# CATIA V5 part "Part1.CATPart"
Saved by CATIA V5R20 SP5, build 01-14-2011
Part number: Part1
Material "Gold Metal": density 7860 kg/m3, Young's modulus 2e+11 Pa, Poisson ratio 0.266
Material "DS Gold": density 7860 kg/m3, Young's modulus 2e+11 Pa, Poisson ratio 0.266
Bounding box of the stored display mesh (mm): x -25 to 25, y -25 to 24.975, z -18 to 18
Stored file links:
  D:\zhonggao\Part1.CATPart
  C:\Program Files\Dassault Systemes\B20\intel_a\startup\materials\Catalog.CATMaterial
  C:\Program Files\Dassault Systemes\B20\intel_a\startup\materials\yellow_env_512x512.jpg
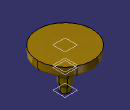
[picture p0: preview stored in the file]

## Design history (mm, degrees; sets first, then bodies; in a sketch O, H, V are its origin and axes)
Body1 (main body)
Body2, material "Gold Metal"
  Plane1: type Offset, RefPlane xy-plane, Offset 2
  Plane2: type Offset, RefPlane Plane1, Offset 2
  Plane3: type Offset, RefPlane Plane2, Offset 2
  Plane4: type Offset, RefPlane Plane3, Offset 2
  Plane5: type Offset, RefPlane Plane4, Offset 2
  Plane6: type Offset, RefPlane Plane5, Offset 2
  Sketch1 on Plane6, origin (0, 0, 12), H (1, 0, 0), V (0, 1, 0)
    circle A1 centre (0, 0) radius 25
    radius A1 = 25
  Sketch2 on Plane5, origin (0, 0, 10), H (1, 0, 0), V (0, 1, 0)
    circle A1 centre (0, 0) radius 24
    radius A1 = 24
  Sketch3 on Plane4, origin (0, 0, 8), H (1, 0, 0), V (0, 1, 0)
    circle A1 centre (0, 0) radius 20
    radius A1 = 20
  Sketch4 on Plane2, origin (0, 0, 4), H (1, 0, 0), V (0, 1, 0)
    circle A1 centre (0, 0) radius 10
    radius A1 = 10
  Sketch5 on Plane1, origin (0, 0, 2), H (1, 0, 0), V (0, 1, 0)
    circle A1 centre (0, 0) radius 5
    radius A1 = 5
  Plane7: type Offset, RefPlane Plane6, Offset 6
  Sketch6 on Plane7, origin (0, 0, 18), H (1, 0, 0), V (0, 1, 0)
    circle A1 centre (0, 0) radius 25
    radius A1 = 25
  Loft1: solid, Sections (Sketch6; Sketch1; Sketch2; Sketch3; Sketch4; Sketch5), EndSectionTangent xy-plane
Body3, material "DS Gold"
  Plane8: type Offset, RefPlane xy-plane, Offset 2, reversed
  Sketch7 on Plane8, origin (0, 0, -2), H (1, 0, 0), V (0, 1, 0)
    circle A1 centre (0, 0) radius 6.5
    radius A1 = 6.5
  Plane9: type Offset, RefPlane Plane8, Offset 4, reversed
  Sketch8 on Plane9, origin (0, 0, -6), H (1, 0, 0), V (0, 1, 0)
    circle A1 centre (0, 0) radius 5.5
    radius A1 = 5.5
  Plane10: type Offset, RefPlane Plane9, Offset 4, reversed
  Sketch9 on Plane10, origin (0, 0, -10), H (1, 0, 0), V (0, 1, 0)
    circle A1 centre (0, 0) radius 5.5
    radius A1 = 5.5
  Plane11: type Offset, RefPlane Plane10, Offset 4, reversed
  Sketch10 on Plane11, origin (0, 0, -14), H (1, 0, 0), V (0, 1, 0)
    circle A1 centre (0, 0) radius 4
    radius A1 = 4
  Plane12: type Offset, RefPlane Plane11, Offset 4, reversed
  Sketch11 on Plane12, origin (0, 0, -18), H (1, 0, 0), V (0, 1, 0)
    circle A1 centre (0, 0) radius 4
    radius A1 = 4
  Plane13: type Offset, RefPlane Plane8, Offset 4
  Sketch12 on Plane13, origin (0, 0, 2), H (1, 0, 0), V (0, 1, 0)
    circle A1 centre (0, 0) radius 5
    radius A1 = 5
  Loft2: solid, Sections (Sketch12; Sketch7; Sketch8; Sketch9; Sketch10; Sketch11)
  Sketch13 on Plane12, origin (0, 0, -18), H (1, 0, 0), V (0, 1, 0)
    circle A1 centre (0, 0) radius 2.5
    radius A1 = 2.5
  Pocket1: profile Sketch13, direction (0, 0, 1), length 5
